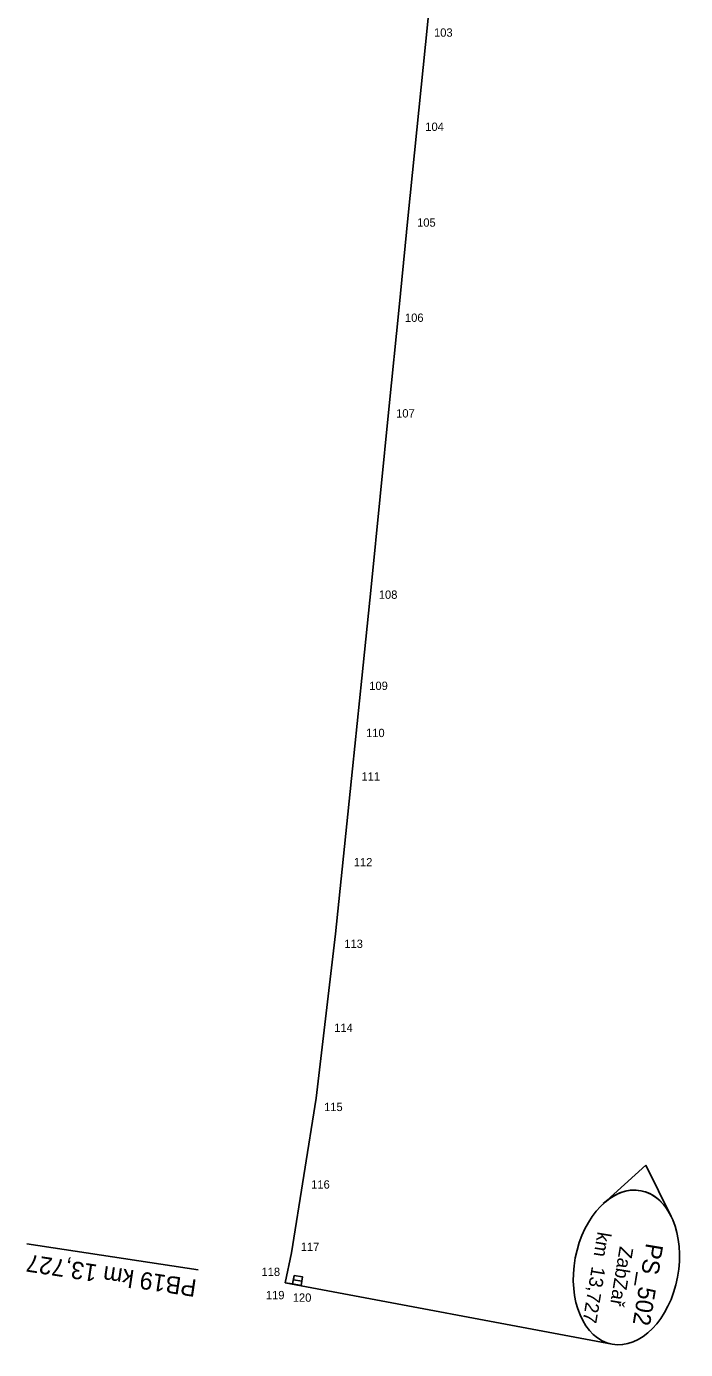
# Model space of a CAD drawing. Extents: x -743397 to -742769, y -1127804 to -1126284.
# Drawn here: x -743396.5 to -743301.5, y -1127804.4 to -1127613.8 of the extents above; entities that cross this region are included whole.
import ezdxf

# ---------------------------------------------------------------- set-up
doc = ezdxf.new("R2010")
doc.units = 0
for name, color, linetype in [('_Násyp', 7, 'Continuous'), ('_Zabezpečovací zařízení', 7, 'Continuous'), ('_Zabezpečovací zařízení_trasa', 7, 'Continuous'), ('bublina_růžová_230_čára_tenká', 7, 'Continuous'), ('bublina_růžová_230_čára_tučná', 7, 'Continuous'), ('křížky', 7, 'Continuous'), ('Nový stav', 7, 'Continuous'), ('Vrstva 60', 7, 'Continuous')]:
    doc.layers.add(name, color=color, linetype=linetype)

# ---------------------------------------------------------------- blocks, each defined once
blk = doc.blocks.new('POINT_DISPLAY')
blk.add_line((0, 0), (0, 0))

msp = doc.modelspace()

# ---------------------------------------------------------------- linework, layer by layer
at = {"layer": '_Zabezpečovací zařízení'}
for p, q in [((-743357.94, -1127793.74), (-743358.15, -1127794.97)), ((-743356.81, -1127794.57), (-743358.04, -1127794.36)), ((-743356.71, -1127793.96), (-743357.94, -1127793.74)), ((-743356.92, -1127795.19), (-743356.71, -1127793.96)), ((-743358.15, -1127794.97), (-743356.92, -1127795.19))]:
    msp.add_line(p, q, dxfattribs=at)
msp.add_lwpolyline([(-743357.94, -1127793.74), (-743358.04, -1127794.36), (-743356.81, -1127794.57), (-743356.71, -1127793.96), (-743357.94, -1127793.74)], dxfattribs=at)
at = {"layer": '_Zabezpečovací zařízení_trasa'}
msp.add_lwpolyline([(-743318.79, -1127415.84), (-743321.57, -1127442.6), (-743324.27, -1127469.35), (-743329.51, -1127521.46), (-743334.23, -1127568.82), (-743338.71, -1127613.56), (-743341.47, -1127641), (-743342.85, -1127654.73), (-743344.22, -1127668.45), (-743346.84, -1127694.61), (-743348.17, -1127707.68), (-743349.5, -1127720.75), (-743351.96, -1127744.53), (-743354.76, -1127768.22), (-743358.32, -1127790.48), (-743359.2, -1127794.79), (-743358.15, -1127794.97)], dxfattribs=at)
at = {"layer": 'bublina_růžová_230_čára_tenká'}
msp.add_line((-743312.1, -1127803.66), (-743359.2, -1127794.79), dxfattribs=at)
at = {"layer": 'bublina_růžová_230_čára_tučná'}
for p, q in [((-743307.25, -1127777.86), (-743313.36, -1127783.41)), ((-743307.25, -1127777.86), (-743313.36, -1127783.41)), ((-743303.57, -1127785.25), (-743307.25, -1127777.86)), ((-743303.57, -1127785.25), (-743307.25, -1127777.86))]:
    msp.add_line(p, q, dxfattribs=at)
msp.add_ellipse((-743310.02, -1127792.6), major_axis=(-2.08, -11.06), ratio=0.666667, dxfattribs=at)
msp.add_ellipse((-743310.02, -1127792.6), major_axis=(2.08, 11.06), ratio=0.666473, start_param=5.557317, end_param=7.009053, dxfattribs=at)
at = {"layer": 'Nový stav'}
msp.add_line((-743371.75, -1127792.95), (-743396.47, -1127789.21), dxfattribs=at)
msp.add_line((-743371.75, -1127792.95), (-743396.47, -1127789.21), dxfattribs=at)
at = {"layer": 'Vrstva 60'}
for p, q in [((-743340.09, -1127627.28), (-743340.09, -1127627.28)), ((-743341.47, -1127641), (-743341.47, -1127641)), ((-743342.85, -1127654.73), (-743342.85, -1127654.73)), ((-743344.22, -1127668.45), (-743344.22, -1127668.45)), ((-743346.84, -1127694.61), (-743346.84, -1127694.61)), ((-743348.17, -1127707.68), (-743348.17, -1127707.68)), ((-743348.84, -1127714.22), (-743348.84, -1127714.22)), ((-743349.5, -1127720.75), (-743349.5, -1127720.75)), ((-743350.73, -1127732.64), (-743350.73, -1127732.64)), ((-743351.96, -1127744.53), (-743351.96, -1127744.53)), ((-743353.36, -1127756.38), (-743353.36, -1127756.38)), ((-743354.76, -1127768.22), (-743354.76, -1127768.22)), ((-743356.54, -1127779.35), (-743356.54, -1127779.35)), ((-743358.32, -1127790.48), (-743358.32, -1127790.48)), ((-743358.76, -1127792.63), (-743358.76, -1127792.63)), ((-743359.2, -1127794.79), (-743359.2, -1127794.79)), ((-743358.15, -1127794.97), (-743358.15, -1127794.97))]:
    msp.add_line(p, q, dxfattribs=at)

# ---------------------------------------------------------------- block references
at = {"layer": 'křížky', "xscale": 10, "yscale": 10, "rotation": 61.14491455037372}
for p in [(-743340.09, -1127627.28), (-743341.47, -1127641), (-743342.85, -1127654.73), (-743344.22, -1127668.45), (-743346.84, -1127694.61), (-743348.17, -1127707.68), (-743348.84, -1127714.22), (-743349.5, -1127720.75), (-743350.73, -1127732.64), (-743351.96, -1127744.53), (-743353.36, -1127756.38), (-743354.76, -1127768.22), (-743356.54, -1127779.35), (-743358.32, -1127790.48), (-743358.76, -1127792.63), (-743359.2, -1127794.79), (-743358.15, -1127794.97)]:
    msp.add_blockref('POINT_DISPLAY', p, dxfattribs=at)

# ---------------------------------------------------------------- texts
at = {"layer": '_Násyp'}
for s, height, p in [('km  13,727', 2, (-743314.18, -1127787.38)), ('ZabZař', 2, (-743310.98, -1127789.49)), ('PS_502', 2.5, (-743307.17, -1127789))]:
    msp.add_text(s, height=height, rotation=260.5528, dxfattribs=at).set_placement(p)
at = {"layer": 'Nový stav'}
msp.add_text('PB19 km 13,727', height=2.5, rotation=171.395, dxfattribs=at).set_placement((-743371.87, -1127794.39))
msp.add_text('PB19 km 13,727', height=2.5, rotation=171.395, dxfattribs=at).set_placement((-743371.87, -1127794.39))
at = {"layer": 'Vrstva 60'}
for s, p in [('103', (-743337.76, -1127615.29)), ('104', (-743339.02, -1127628.86)), ('105', (-743340.2, -1127642.66)), ('106', (-743341.95, -1127656.37)), ('107', (-743343.22, -1127670.15)), ('108', (-743345.72, -1127696.27)), ('109', (-743347.1, -1127709.4)), ('110', (-743347.56, -1127716.19)), ('111', (-743348.22, -1127722.46)), ('112', (-743349.33, -1127734.81)), ('113', (-743350.69, -1127746.57)), ('114', (-743352.15, -1127758.67)), ('115', (-743353.61, -1127770.07)), ('116', (-743355.47, -1127781.24)), ('117', (-743356.97, -1127790.22)), ('118', (-743362.63, -1127793.83)), ('119', (-743362, -1127797.18)), ('120', (-743358.12, -1127797.54))]:
    msp.add_text(s, height=1.2, dxfattribs=at).set_placement(p)

doc.saveas('drawing.dxf')
